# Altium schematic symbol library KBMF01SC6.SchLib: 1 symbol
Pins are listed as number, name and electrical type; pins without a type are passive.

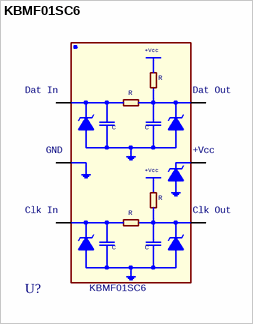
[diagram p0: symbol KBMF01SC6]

## KBMF01SC6
designator U?
footprint ST_SOT23-6L
pins: 1 Dat In, 2 GND, 3 Clk In, 4 Clk Out, 5 +Vcc, 6 Dat Out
